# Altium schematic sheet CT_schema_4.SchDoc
size 284 x 243 mm
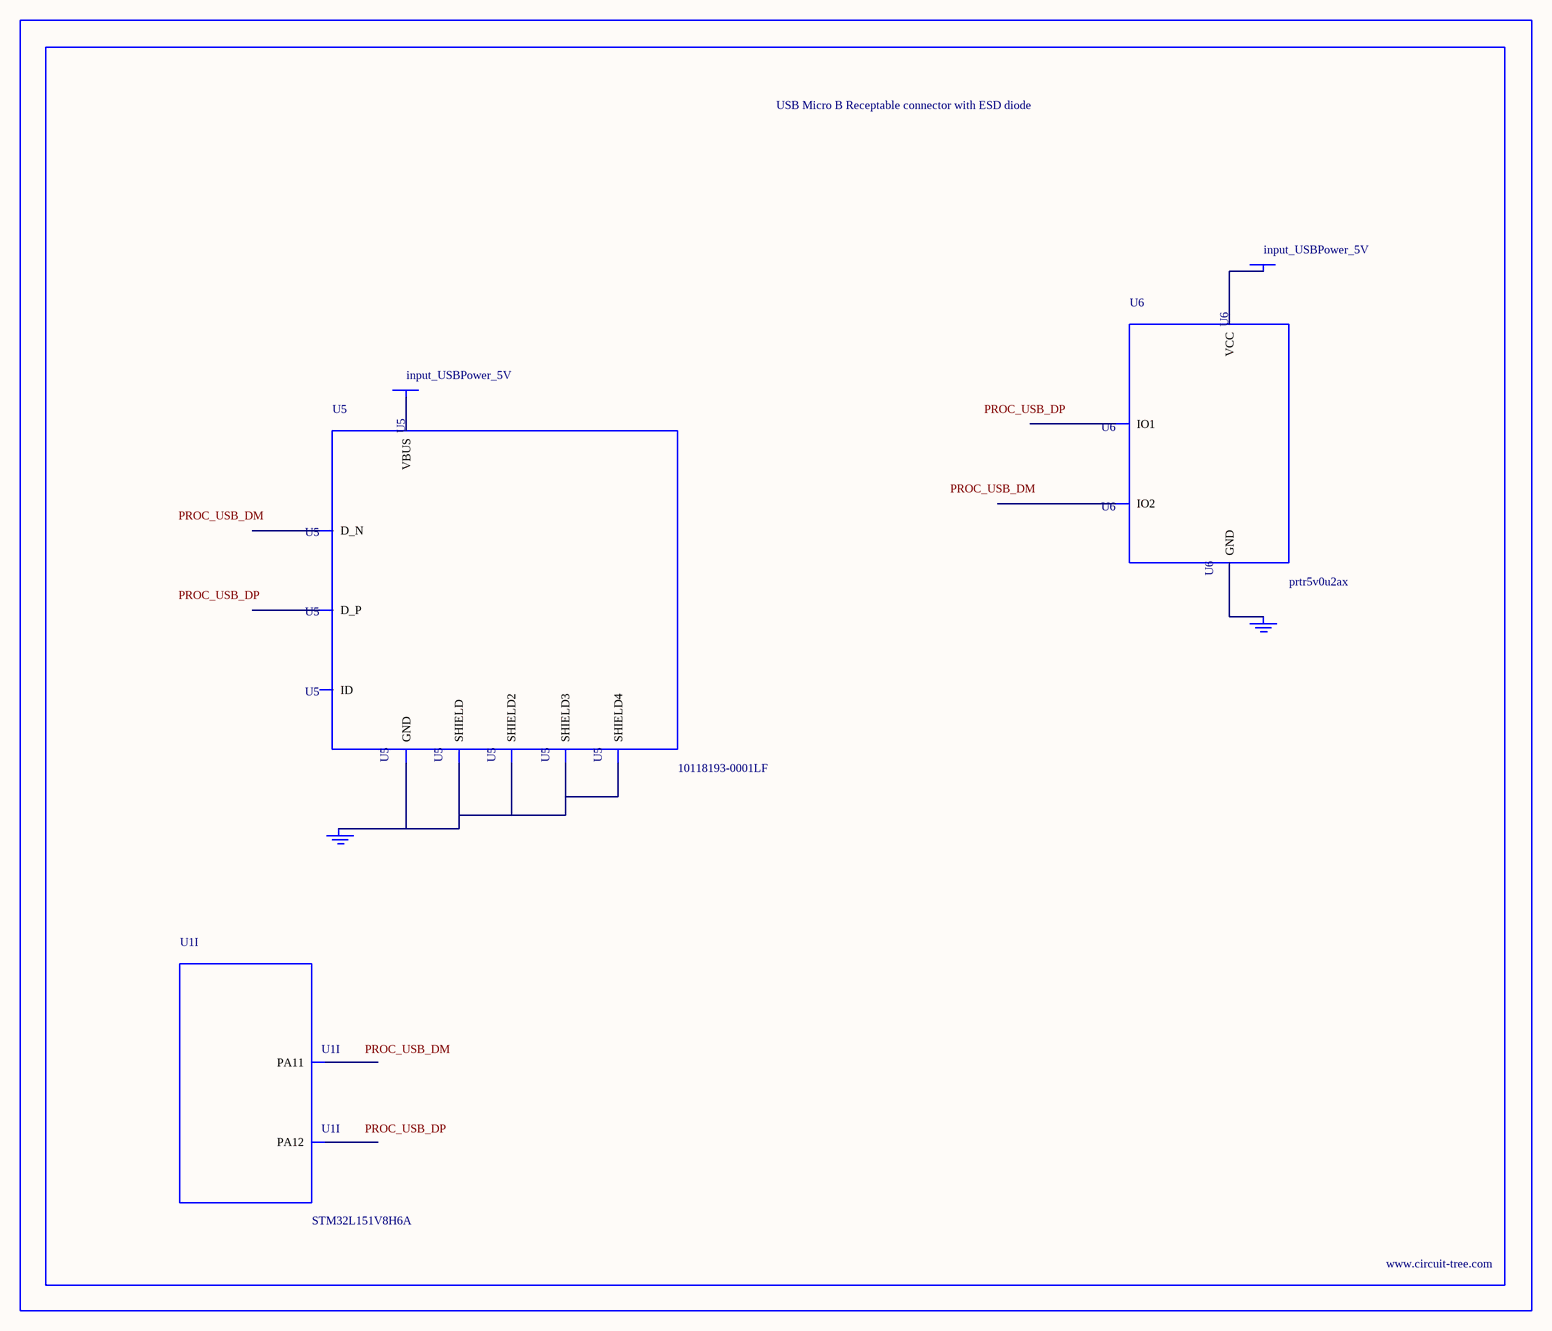
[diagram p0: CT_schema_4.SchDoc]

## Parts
BORDER3  (no value)
GND_INSTANCE_3_0  (no value)
GND_INSTANCE_3_1  (no value)
POWER_INSTANCE_3_0  input_USBPower_5V
POWER_INSTANCE_3_1  input_USBPower_5V
U1  STM32L151V8H6A  [UFBGA100]  (part I of 9)
U5  10118193-0001LF  [FCI_10118193-0001LF]
U6  prtr5v0u2ax  [SOT143B]

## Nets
NetGND_INSTANCE_3_0_0: GND_INSTANCE_3_0.0(GND) U5.5(GND) U5.6(SHIELD) U5.7(SHIELD2) U5.8(SHIELD3) U5.9(SHIELD4)
NetGND_INSTANCE_3_1_0: GND_INSTANCE_3_1.0(GND) U6.1(GND)
NetPOWER_INSTANCE_3_0_0: POWER_INSTANCE_3_0.0(PWR) U5.1(VBUS)
NetPOWER_INSTANCE_3_1_0: POWER_INSTANCE_3_1.0(PWR) U6.4(VCC)

Not connected (* = marked no-connect by the designer): U1 A12(PA12) B12(PA11); U5 2(D_N) 3(D_P) 4(ID); U6 2(IO1) 3(IO2)

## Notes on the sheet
- Labels drawn without touching a wire or pin: PROC_USB_DM, PROC_USB_DP

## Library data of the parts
BORDER3 = BORDER_PAGE3
GND_INSTANCE_3_0 GND_INSTANCE_3_1 = GND
POWER_INSTANCE_3_0 POWER_INSTANCE_3_1 = PWR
